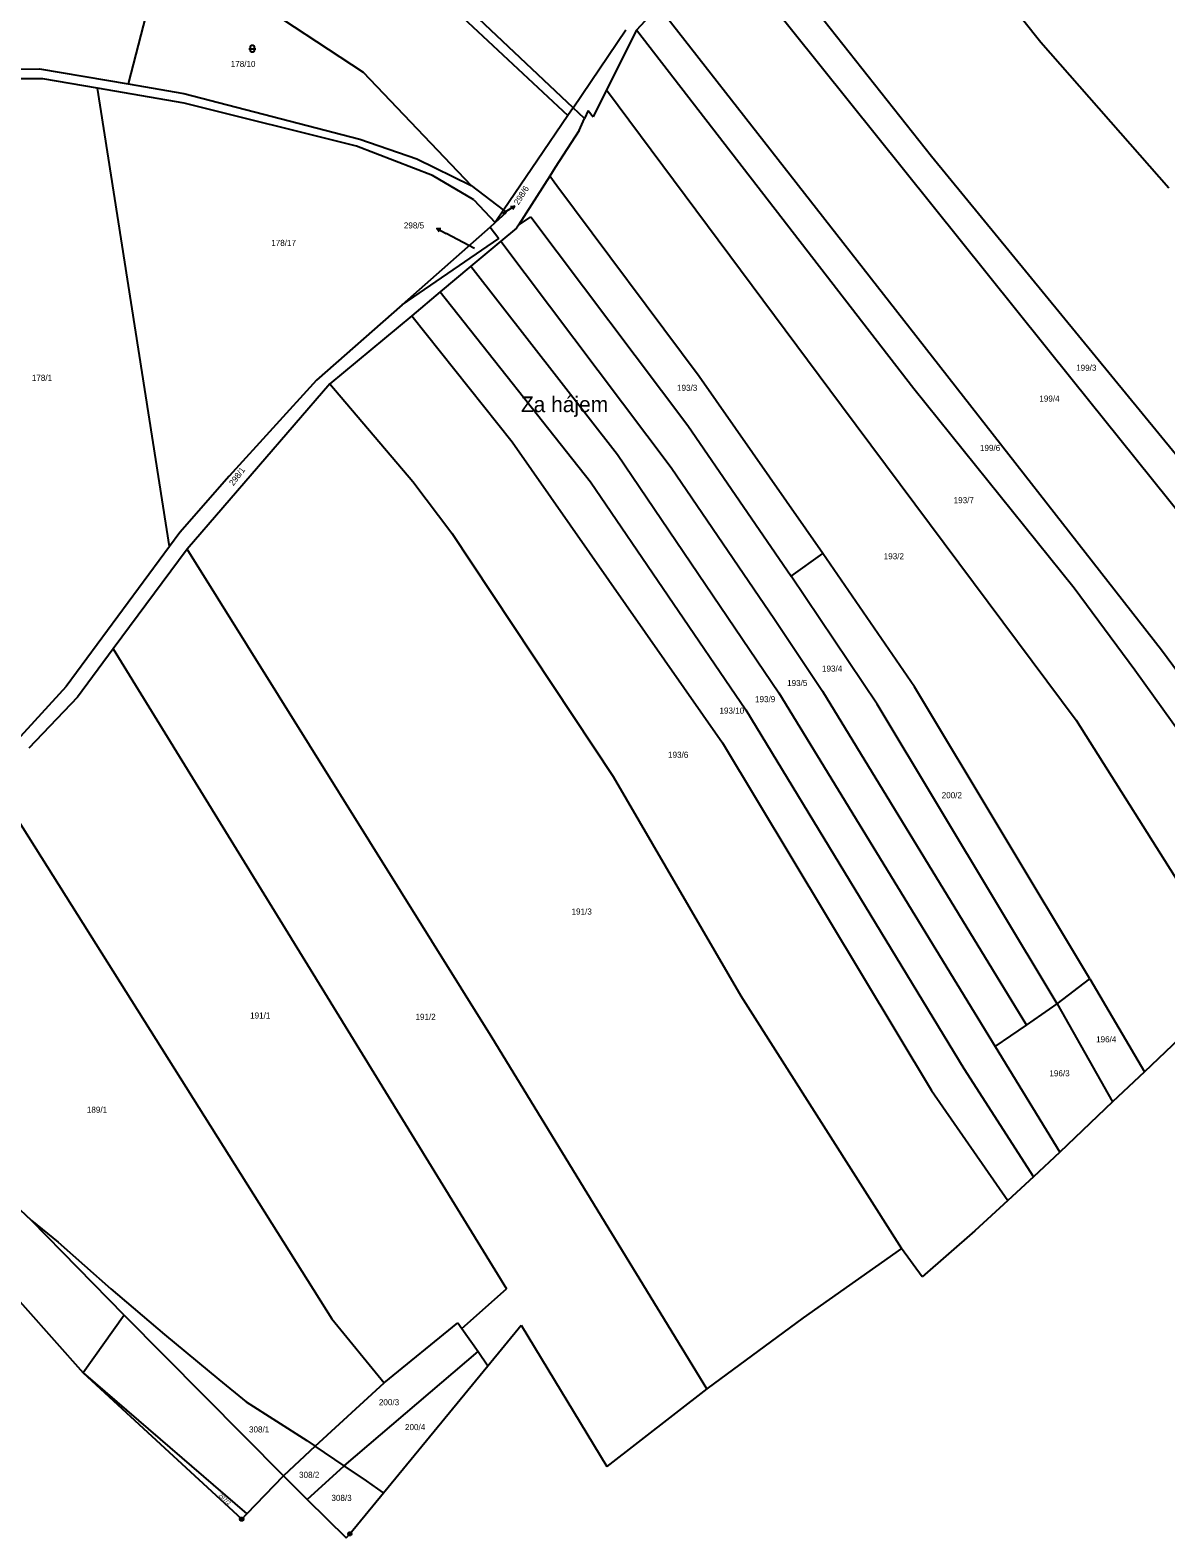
# Model space of a CAD drawing. Extents: x -780000 to -777378, y -1011169 to -1009297.
# Drawn here: x -779291.4 to -778972.3, y -1011169.3 to -1010745.7 of the extents above; entities that cross this region are included whole.
import ezdxf

# ---------------------------------------------------------------- set-up
doc = ezdxf.new("R2010")
doc.units = 0
for name, color, linetype in [('Default', 7, 'Continuous'), ('KN_HRANICE', 7, 'Continuous'), ('KN_KULTURY', 7, 'Continuous'), ('KN_PARCELY', 7, 'Continuous'), ('KN_SLUCKY', 7, 'Continuous')]:
    doc.layers.add(name, color=color, linetype=linetype)

# ---------------------------------------------------------------- blocks, each defined once
blk = doc.blocks.new('316')
at = {"layer": 'Default'}
for points in [[(-1, 1), (0.27, 1), (1, 1)], [(-0.5, 1.5), (-0.4, 1.79), (-0.15, 1.97), (0.16, 1.97), (0.41, 1.79), (0.51, 1.5), (0.51, 0.5), (0.41, 0.21), (0.16, 0.03), (-0.15, 0.03), (-0.4, 0.21), (-0.5, 0.5), (-0.5, 1.5)]]:
    blk.add_lwpolyline(points, dxfattribs=at)
blk = doc.blocks.new('10292')
at = {"layer": 'Default'}
blk.add_line((0, 3), (0, 0), dxfattribs=at)
blk.add_lwpolyline([(-0.5, 2), (0, 3), (0.5, 2)], dxfattribs=at)
blk = doc.blocks.new('105')
at = {"layer": 'Default'}
blk.add_line((-0.12, 0), (0.12, 0), dxfattribs=at)
blk.add_lwpolyline([(0.15, 0.48), (0.4, 0.3), (0.5, 0.01), (0.4, -0.28), (0.15, -0.46), (-0.16, -0.46), (-0.41, -0.28), (-0.51, 0.01), (-0.41, 0.3), (-0.16, 0.48), (0.15, 0.48)], dxfattribs=at)

msp = doc.modelspace()

# ---------------------------------------------------------------- linework, layer by layer
at = {"layer": 'KN_HRANICE'}
for p, q in [((-779090.15, -1010715.21), (-779038.14, -1010781.12)), ((-779034.27, -1010715.3), (-779007.39, -1010749.08)), ((-778998.61, -1010843.93), (-779096.96, -1010721.21)), ((-779255.21, -1010727.12), (-779263.87, -1010760.8)), ((-779246.07, -1010725.76), (-779197.77, -1010757.47)), ((-779138.78, -1010767.46), (-779171.89, -1010736.2)), ((-779174.03, -1010738.22), (-779140.28, -1010769.67)), ((-779121, -1010745.73), (-779114.85, -1010739.08)), ((-779114.85, -1010739.08), (-779044.24, -1010829.34)), ((-779138.78, -1010767.46), (-779124.03, -1010745.63)), ((-779121, -1010745.73), (-779129.44, -1010762.47)), ((-779043.05, -1010846.46), (-779121, -1010745.73)), ((-779007.39, -1010749.08), (-778971.37, -1010789.97)), ((-779295.87, -1010756.68), (-779288.73, -1010756.56)), ((-779288.73, -1010756.56), (-779263.87, -1010760.8)), ((-779197.77, -1010757.47), (-779167.5, -1010789.36)), ((-779287.82, -1010759.31), (-779295.7, -1010759.39)), ((-779272.43, -1010762.01), (-779287.82, -1010759.31)), ((-779252.21, -1010890.71), (-779272.43, -1010762.01)), ((-779248.15, -1010766.16), (-779272.43, -1010762.01)), ((-779263.87, -1010760.8), (-779248.18, -1010763.48)), ((-779248.18, -1010763.48), (-779198.78, -1010776.27)), ((-779129.44, -1010762.47), (-779133.14, -1010770)), ((-779129.44, -1010762.47), (-779063.39, -1010851.12)), ((-779199.71, -1010778.27), (-779248.15, -1010766.16)), ((-779138.78, -1010767.46), (-779140.28, -1010769.67)), ((-779135.61, -1010770.46), (-779138.78, -1010767.46)), ((-779140.28, -1010769.67), (-779148.79, -1010782.17)), ((-779137.14, -1010773.83), (-779135.61, -1010770.46)), ((-779134.58, -1010768.25), (-779135.61, -1010770.46)), ((-779134.58, -1010768.25), (-779133.14, -1010770)), ((-779137.14, -1010773.83), (-779143.83, -1010784.29)), ((-779178.37, -1010786.48), (-779199.71, -1010778.27)), ((-779198.78, -1010776.27), (-779182.71, -1010781.86)), ((-779182.71, -1010781.86), (-779167.5, -1010789.36)), ((-779148.79, -1010782.17), (-779158.36, -1010796.23)), ((-779143.83, -1010784.29), (-779145.37, -1010786.69)), ((-779038.14, -1010781.12), (-778964.83, -1010870.44)), ((-779166.68, -1010793.33), (-779178.37, -1010786.48)), ((-779145.37, -1010786.69), (-779154.19, -1010800.5)), ((-779143.35, -1010789.4), (-779145.37, -1010786.69)), ((-779167.5, -1010789.36), (-779158.36, -1010796.23)), ((-779103.43, -1010842.99), (-779143.35, -1010789.4)), ((-779166.68, -1010793.33), (-779160.74, -1010799.73)), ((-779158.36, -1010796.23), (-779160.74, -1010799.73)), ((-779160.74, -1010799.73), (-779157.56, -1010796.83)), ((-779158.36, -1010796.23), (-779157.56, -1010796.83)), ((-779162.08, -1010801.02), (-779186.85, -1010822.84)), ((-779162.08, -1010801.02), (-779160.74, -1010799.73)), ((-779162.08, -1010801.02), (-779159.66, -1010804.24)), ((-779154.73, -1010801.34), (-779159.1, -1010804.99)), ((-779154.19, -1010800.5), (-779154.73, -1010801.34)), ((-779154.19, -1010800.5), (-779150.71, -1010798.11)), ((-779150.71, -1010798.11), (-779106.53, -1010856.72)), ((-779186.85, -1010822.84), (-779159.66, -1010804.24)), ((-779159.1, -1010804.99), (-779167.52, -1010812.01)), ((-779159.1, -1010804.99), (-779111.3, -1010868.53)), ((-779167.52, -1010812.01), (-779176.17, -1010819.22)), ((-779167.52, -1010812.01), (-779126.3, -1010864.94)), ((-779186.85, -1010822.84), (-779210.91, -1010844.02)), ((-779176.17, -1010819.22), (-779184.17, -1010825.9)), ((-779176.17, -1010819.22), (-779133.97, -1010872.59)), ((-779184.17, -1010825.9), (-779207.15, -1010845.06)), ((-779184.17, -1010825.9), (-779155.93, -1010861.31)), ((-779044.24, -1010829.34), (-778973.49, -1010919.73)), ((-779068.64, -1010892.72), (-779103.43, -1010842.99)), ((-778900.11, -1010966.64), (-778998.61, -1010843.93)), ((-779207.15, -1010845.06), (-779247.3, -1010891.46)), ((-779210.91, -1010844.02), (-779235.44, -1010870.94)), ((-779207.15, -1010845.06), (-779183.86, -1010872.45)), ((-778998.02, -1010902.45), (-779043.05, -1010846.46)), ((-779063.39, -1010851.12), (-778997.44, -1010939.52)), ((-779106.53, -1010856.72), (-779077.58, -1010899.08)), ((-779155.93, -1010861.31), (-779096.86, -1010945.95)), ((-779126.3, -1010864.94), (-779081.05, -1010931.89)), ((-779111.3, -1010868.53), (-779082.24, -1010911.14)), ((-779235.44, -1010870.94), (-779249.3, -1010886.77)), ((-779183.86, -1010872.45), (-779172.91, -1010886.98)), ((-779133.97, -1010872.59), (-779090.28, -1010936.59)), ((-779249.3, -1010886.77), (-779252.21, -1010890.71)), ((-779172.91, -1010886.98), (-779127.56, -1010955.39)), ((-779252.21, -1010890.71), (-779281.31, -1010930.07)), ((-779247.3, -1010891.46), (-779268.1, -1010919.48)), ((-779161.56, -1011028.82), (-779247.3, -1010891.46)), ((-779077.58, -1010899.08), (-779068.64, -1010892.72)), ((-779042.92, -1010930.15), (-779068.64, -1010892.72)), ((-779053.4, -1010935.08), (-779077.58, -1010899.08)), ((-778980.97, -1010925.46), (-778998.02, -1010902.45)), ((-779082.24, -1010911.14), (-779068.7, -1010931.41)), ((-779268.1, -1010919.48), (-779278.06, -1010933.1)), ((-779268.1, -1010919.48), (-779212.73, -1011009.48)), ((-778973.49, -1010919.73), (-778924.2, -1010986.99)), ((-778944.73, -1010976.05), (-778980.97, -1010925.46)), ((-779281.31, -1010930.07), (-779295.1, -1010945.28)), ((-779081.05, -1010931.89), (-779020.18, -1011031.25)), ((-779068.7, -1010931.41), (-779011.43, -1011025.21)), ((-778993.64, -1011012.17), (-779042.92, -1010930.15)), ((-779278.06, -1010933.1), (-779291.76, -1010947.43)), ((-779090.28, -1010936.59), (-779029.06, -1011037.37)), ((-779002.79, -1011019.26), (-779053.4, -1010935.08)), ((-778997.44, -1010939.52), (-778964.98, -1010991)), ((-779096.86, -1010945.95), (-779038.09, -1011043.59)), ((-779127.56, -1010955.39), (-779091.73, -1011017)), ((-779300.33, -1010958.9), (-779206.63, -1011107.76)), ((-779212.73, -1011009.48), (-779157.5, -1011099.26)), ((-779002.79, -1011019.26), (-778993.64, -1011012.17)), ((-778993.64, -1011012.17), (-778978.29, -1011038.33)), ((-778951.63, -1011012.88), (-778978.29, -1011038.33)), ((-779091.73, -1011017), (-779046.54, -1011087.97)), ((-779011.43, -1011025.21), (-779002.79, -1011019.26)), ((-779002.79, -1011019.26), (-778987.21, -1011046.72)), ((-779020.18, -1011031.25), (-779011.43, -1011025.21)), ((-779101.21, -1011127.39), (-779161.56, -1011028.82)), ((-779020.18, -1011031.25), (-779002, -1011060.92)), ((-779029.06, -1011037.37), (-779009.48, -1011067.84)), ((-778978.29, -1011038.33), (-778987.21, -1011046.72)), ((-779333.53, -1011040.14), (-779291.02, -1011080.11)), ((-779038.09, -1011043.59), (-779016.68, -1011074.49)), ((-778987.21, -1011046.72), (-779002, -1011060.92)), ((-779002, -1011060.92), (-779009.48, -1011067.84)), ((-779009.48, -1011067.84), (-779016.68, -1011074.49)), ((-779320.15, -1011073.73), (-779276.53, -1011122.92)), ((-779016.68, -1011074.49), (-779025.91, -1011083.02)), ((-779291.02, -1011080.11), (-779283.53, -1011086.19)), ((-779264.99, -1011106.72), (-779291.02, -1011080.11)), ((-779025.91, -1011083.02), (-779040.69, -1011095.95)), ((-779283.53, -1011086.19), (-779268.67, -1011099.29)), ((-779046.54, -1011087.97), (-779074.2, -1011107.44)), ((-779040.69, -1011095.95), (-779046.54, -1011087.97)), ((-779268.67, -1011099.29), (-779253.59, -1011112.14)), ((-779170.13, -1011110.43), (-779157.5, -1011099.26)), ((-779264.99, -1011106.72), (-779220.18, -1011151.87)), ((-779206.63, -1011107.76), (-779191.88, -1011125.67)), ((-779191.88, -1011125.67), (-779171.25, -1011108.84)), ((-779171.25, -1011108.84), (-779170.13, -1011110.43)), ((-779170.13, -1011110.43), (-779165.54, -1011116.95)), ((-779162.74, -1011120.93), (-779153.37, -1011109.53)), ((-779153.37, -1011109.53), (-779129.33, -1011149.2)), ((-779074.2, -1011107.44), (-779101.21, -1011127.39)), ((-779253.59, -1011112.14), (-779238.35, -1011124.82)), ((-779203.15, -1011149.01), (-779165.54, -1011116.95)), ((-779165.54, -1011116.95), (-779162.74, -1011120.93)), ((-779276.53, -1011122.92), (-779230.46, -1011162.5)), ((-779269.1, -1011129.77), (-779276.53, -1011122.92)), ((-779192.08, -1011156.62), (-779162.74, -1011120.93)), ((-779238.35, -1011124.82), (-779230.65, -1011131.07)), ((-779211.28, -1011143.53), (-779191.88, -1011125.67)), ((-779101.21, -1011127.39), (-779129.33, -1011149.2)), ((-779231.93, -1011164.02), (-779269.1, -1011129.77)), ((-779230.65, -1011131.07), (-779213.67, -1011141.92)), ((-779211.28, -1011143.53), (-779220.18, -1011151.87)), ((-779213.67, -1011141.92), (-779211.28, -1011143.53)), ((-779203.15, -1011149.01), (-779211.28, -1011143.53)), ((-779230.46, -1011162.5), (-779220.18, -1011151.87)), ((-779220.18, -1011151.87), (-779213.5, -1011158.46)), ((-779213.5, -1011158.46), (-779203.15, -1011149.01)), ((-779196.84, -1011153.26), (-779203.15, -1011149.01)), ((-779201.55, -1011168.14), (-779192.08, -1011156.62)), ((-779192.08, -1011156.62), (-779196.84, -1011153.26)), ((-779213.5, -1011158.46), (-779202.55, -1011169.26)), ((-779231.93, -1011164.02), (-779230.46, -1011162.5)), ((-779202.55, -1011169.26), (-779201.55, -1011168.14))]:
    msp.add_line(p, q, dxfattribs=at)
at = {"layer": 'KN_PARCELY'}
for p, q in [((-779158.56, -1010797.19), (-779157.83, -1010796.73)), ((-779166.51, -1010807.07), (-779174.48, -1010802.81))]:
    msp.add_line(p, q, dxfattribs=at)
at = {"layer": 'KN_SLUCKY'}
msp.add_line((-779264.99, -1011106.72), (-779276.53, -1011122.92), dxfattribs=at)

# ---------------------------------------------------------------- block references
at = {"layer": 'KN_KULTURY'}
msp.add_blockref('316', (-779228.96, -1010751.91), dxfattribs=at)
at = {"layer": 'KN_PARCELY'}
for p, rotation in [((-779157.83, -1010796.73), -57.70746700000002), ((-779174.48, -1010802.81), 61.822146)]:
    msp.add_blockref('10292', p, dxfattribs=dict(at, rotation=rotation))
for p in [(-779231.93, -1011164.02), (-779201.55, -1011168.14)]:
    msp.add_blockref('105', p, dxfattribs=at)

# ---------------------------------------------------------------- texts
for s, height, p in [('178/10', 1.7, (-779235.02, -1010756.02)), ('298/5', 1.7, (-779186.37, -1010801.39)), ('178/17', 1.7, (-779223.64, -1010806.29)), ('298/5', 0.1, (-779166.5, -1010807.07)), ('199/3', 1.7, (-778997.46, -1010841.39)), ('178/1', 1.7, (-779290.91, -1010844.21)), ('193/3', 1.7, (-779109.61, -1010847.01)), ('199/4', 1.7, (-779007.79, -1010850.04)), ('Za hájem', 4.4, (-779153.49, -1010853)), ('199/6', 1.7, (-779024.49, -1010863.89)), ('193/7', 1.7, (-779031.88, -1010878.58)), ('193/2', 1.7, (-779051.53, -1010894.33)), ('193/4', 1.7, (-779068.87, -1010925.9)), ('193/5', 1.7, (-779078.68, -1010929.95)), ('193/9', 1.7, (-779087.7, -1010934.48)), ('193/10', 1.7, (-779097.69, -1010937.7)), ('193/6', 1.7, (-779112.14, -1010950.1)), ('200/2', 1.7, (-779035.24, -1010961.47)), ('191/3', 1.7, (-779139.25, -1010994.15)), ('191/1', 1.7, (-779229.58, -1011023.36)), ('191/2', 1.7, (-779183.11, -1011023.73)), ('196/4', 1.7, (-778991.85, -1011030.04)), ('196/3', 1.7, (-779004.97, -1011039.59)), ('189/1', 1.7, (-779275.45, -1011049.83)), ('200/3', 1.7, (-779193.39, -1011132)), ('308/1', 1.7, (-779229.89, -1011139.65)), ('200/4', 1.7, (-779186.05, -1011139)), ('308/2', 1.7, (-779215.82, -1011152.39)), ('308/3', 1.7, (-779206.73, -1011158.88))]:
    msp.add_text(s, height=height, dxfattribs=at).set_placement(p)
for s, height, rotation, p in [('298/6', 1.7, 57.64, (-779154.16, -1010794.93)), ('298/6', 0.1, 57.124, (-779158.56, -1010797.18)), ('298/1', 1.7, 53.113, (-779234.28, -1010873.83)), ('297/2', 1.14, 317.591, (-779238.55, -1011157.46))]:
    msp.add_text(s, height=height, rotation=rotation, dxfattribs=at).set_placement(p)

doc.saveas('drawing.dxf')
